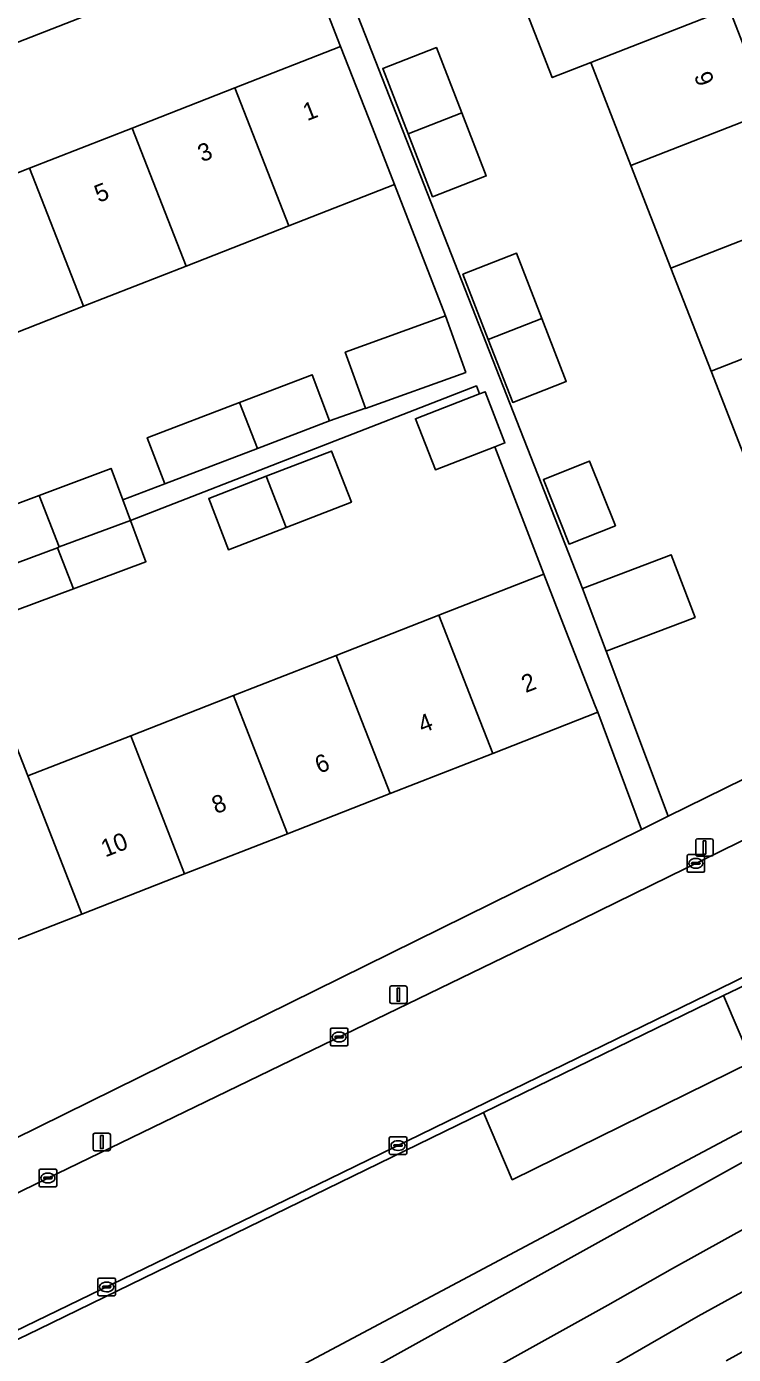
# Model space of a CAD drawing. Extents: x 159680 to 160786, y 387323 to 388340.
# Drawn here: x 160243.7 to 160284, y 387463 to 387538.8 of the extents above; entities that cross this region are included whole.
import ezdxf

# ---------------------------------------------------------------- set-up
doc = ezdxf.new("R2010")
doc.units = 0
for name, color, linetype in [('IMGEO_Erf', 7, 'Continuous'), ('IMGEO_Fietspad_open', 7, 'Continuous'), ('IMGEO_Groenvoorziening', 7, 'Continuous'), ('IMGEO_Kolk', 7, 'Continuous'), ('IMGEO_Lichtmast', 7, 'Continuous'), ('IMGEO_Pand', 7, 'Continuous'), ('IMGEO_Pand_nummerreeks', 7, 'Continuous'), ('IMGEO_Rijbaan_lokaal_open', 7, 'Continuous'), ('IMGEO_Voetpad_open', 7, 'Continuous')]:
    doc.layers.add(name, color=color, linetype=linetype)

msp = doc.modelspace()

# ---------------------------------------------------------------- linework, layer by layer
at = {"layer": 'IMGEO_Erf'}
for points in [[(160275.893, 387536.722), (160273.69, 387535.863), (160271.402, 387541.734), (160273.605, 387542.592), (160271.263, 387548.602), (160279.163, 387551.682), (160281.506, 387545.671), (160283.794, 387539.801), (160286.081, 387533.932), (160288.369, 387528.062), (160290.657, 387522.192), (160292.945, 387516.322), (160295.286, 387510.315), (160287.386, 387507.236), (160285.045, 387513.243), (160282.757, 387519.113), (160280.469, 387524.983), (160278.181, 387530.853)], [(160243.826, 387530.687), (160249.693, 387532.984), (160255.559, 387535.28), (160261.594, 387537.642), (160259.073, 387544.104), (160205.916, 387523.37), (160208.461, 387516.845), (160214.493, 387519.206), (160220.36, 387521.502), (160226.226, 387523.799), (160232.093, 387526.095), (160237.96, 387528.391)], [(160269.916, 387530.256), (160266.852, 387529.064), (160265.456, 387532.655), (160264.006, 387536.382), (160267.07, 387537.573), (160268.518, 387533.848)], [(160273.094, 387522.108), (160274.491, 387518.517), (160271.427, 387517.325), (160270.031, 387520.915), (160268.581, 387524.643), (160271.645, 387525.834)], [(160254.062, 387511.834), (160257.35, 387513.104), (160261.076, 387514.543), (160262.215, 387511.629), (160258.488, 387510.191), (160255.189, 387508.916)], [(160275.822, 387513.975), (160277.292, 387510.285), (160274.648, 387509.232), (160273.178, 387512.922)], [(160278.786, 387492.941), (160276.288, 387499.632), (160270.292, 387497.289), (160264.424, 387494.996), (160258.556, 387492.703), (160252.688, 387490.41), (160246.82, 387488.116), (160240.952, 387485.823), (160235.084, 387483.53), (160229.216, 387481.237), (160223.218, 387478.893), (160227.723, 387467.872), (160241.485, 387474.571)]]:
    msp.add_lwpolyline(points, close=True, dxfattribs=at)
for points in [[(160260.298, 387545.217), (160260.495, 387544.659), (160260.565, 387544.686), (160260.501, 387544.952), (160260.459, 387545.227), (160260.442, 387545.504), (160260.45, 387545.782), (160260.482, 387546.058), (160260.538, 387546.33), (160260.618, 387546.596), (160260.721, 387546.854), (160260.846, 387547.102), (160263.113, 387548.017), (160263.29, 387545.707), (160263.076, 387545.631), (160264.519, 387541.798), (160262.008, 387540.853), (160275.412, 387506.704), (160280.486, 387508.629), (160281.844, 387505.049), (160276.77, 387503.124), (160280.318, 387493.696), (160290.044, 387498.486)], [(160238.972, 387509.987), (160244.379, 387512.012), (160248.487, 387513.55), (160249.155, 387511.767), (160251.558, 387512.667), (160250.552, 387515.301), (160255.824, 387517.316), (160259.965, 387518.897), (160260.971, 387516.264), (160263.015, 387517.003), (160261.863, 387520.187), (160267.583, 387522.257), (160264.677, 387529.767), (160258.641, 387527.405), (160252.775, 387525.108), (160246.908, 387522.812), (160241.042, 387520.516)], [(160242.477, 387499.229), (160243.739, 387496), (160249.608, 387498.294), (160253.974, 387500), (160255.476, 387500.587), (160261.344, 387502.88), (160267.211, 387505.173), (160273.207, 387507.516), (160270.399, 387514.789), (160267.01, 387513.481), (160265.872, 387516.394), (160269.53, 387517.807), (160269.353, 387518.266), (160249.598, 387510.584), (160250.479, 387508.231), (160246.335, 387506.679), (160243.13, 387505.479)]]:
    msp.add_lwpolyline(points, dxfattribs=at)
at = {"layer": 'IMGEO_Fietspad_open'}
msp.add_lwpolyline([(160283.621, 387462.603), (160296.695, 387469.852), (160300.001, 387472.11), (160301.207, 387473.161), (160302.845, 387474.524), (160305.717, 387478.074), (160304.637, 387480.044), (160301.617, 387477.461), (160298.558, 387474.843), (160297.951, 387474.363), (160295.506, 387472.609), (160294.842, 387472.203), (160282.017, 387465.159), (160277.159, 387462.365)], dxfattribs=at)
at = {"layer": 'IMGEO_Groenvoorziening'}
for points in [[(160304.976, 387485.635), (160305.378, 387490.681), (160303.29, 387492.695), (160299.837, 387491.263), (160294.558, 387488.872), (160284.429, 387483.931), (160284.303, 387483.869), (160283.478, 387483.467), (160285.084, 387479.686), (160271.406, 387472.947), (160269.768, 387476.788), (160244.367, 387464.412), (160217.091, 387451.27)], [(160262.249, 387457.676), (160276.867, 387465.794), (160280.554, 387467.888), (160297.076, 387477.04)]]:
    msp.add_lwpolyline(points, dxfattribs=at)
for points in [[(160283.478, 387483.467), (160270.499, 387477.144), (160269.768, 387476.788), (160271.406, 387472.947), (160285.084, 387479.686)], [(160286.787, 387476.926), (160287.418, 387475.529), (160246.566, 387452.847), (160245.582, 387455.016)], [(160287.418, 387475.529), (160286.787, 387476.926), (160245.582, 387455.016), (160246.566, 387452.847)]]:
    msp.add_lwpolyline(points, close=True, dxfattribs=at)
at = {"layer": 'IMGEO_Kolk'}
for p, q in [((160281.463, 387491.509), (160282.315, 387491.509)), ((160281.388, 387490.583), (160281.388, 387491.435)), ((160281.647, 387491.003), (160281.647, 387491.015)), ((160282.085, 387490.966), (160281.687, 387490.966)), ((160281.69, 387491.052), (160282.088, 387491.052)), ((160281.899, 387490.729), (160281.874, 387490.729)), ((160281.876, 387491.289), (160281.901, 387491.289)), ((160282.131, 387491.015), (160282.131, 387491.003)), ((160282.389, 387491.435), (160282.389, 387490.583)), ((160282.315, 387490.509), (160281.463, 387490.509)), ((160261.091, 387481.597), (160261.943, 387481.597)), ((160261.016, 387480.671), (160261.016, 387481.523)), ((160261.275, 387481.091), (160261.275, 387481.103)), ((160261.713, 387481.054), (160261.315, 387481.054)), ((160261.318, 387481.14), (160261.716, 387481.14)), ((160261.504, 387481.377), (160261.529, 387481.377)), ((160261.759, 387481.103), (160261.759, 387481.091)), ((160262.017, 387481.523), (160262.017, 387480.671)), ((160261.943, 387480.597), (160261.091, 387480.597)), ((160261.527, 387480.817), (160261.502, 387480.817)), ((160264.38, 387474.474), (160264.38, 387475.326)), ((160264.455, 387475.4), (160265.307, 387475.4)), ((160264.639, 387474.894), (160264.639, 387474.906)), ((160265.077, 387474.857), (160264.679, 387474.857)), ((160264.682, 387474.943), (160265.08, 387474.943)), ((160264.868, 387475.18), (160264.893, 387475.18)), ((160265.123, 387474.906), (160265.123, 387474.894)), ((160265.381, 387475.326), (160265.381, 387474.474)), ((160265.307, 387474.4), (160264.455, 387474.4)), ((160264.891, 387474.62), (160264.866, 387474.62)), ((160244.378, 387472.622), (160244.378, 387473.474)), ((160244.453, 387473.548), (160245.305, 387473.548)), ((160244.866, 387473.328), (160244.891, 387473.328)), ((160245.379, 387473.474), (160245.379, 387472.622)), ((160245.305, 387472.548), (160244.453, 387472.548)), ((160244.637, 387473.042), (160244.637, 387473.054)), ((160245.075, 387473.005), (160244.677, 387473.005)), ((160244.68, 387473.091), (160245.078, 387473.091)), ((160244.889, 387472.768), (160244.864, 387472.768)), ((160245.121, 387473.054), (160245.121, 387473.042)), ((160247.733, 387466.405), (160247.733, 387467.257)), ((160247.808, 387467.331), (160248.66, 387467.331)), ((160248.734, 387467.257), (160248.734, 387466.405)), ((160247.992, 387466.825), (160247.992, 387466.837)), ((160248.43, 387466.788), (160248.032, 387466.788)), ((160248.035, 387466.874), (160248.433, 387466.874)), ((160248.244, 387466.551), (160248.219, 387466.551)), ((160248.221, 387467.111), (160248.246, 387467.111)), ((160248.476, 387466.837), (160248.476, 387466.825)), ((160248.66, 387466.331), (160247.808, 387466.331))]:
    msp.add_line(p, q, dxfattribs=at)
for points in [[(160281.463, 387491.509), (160282.315, 387491.509)], [(160281.388, 387490.583), (160281.388, 387491.435)], [(160282.389, 387491.435), (160282.389, 387490.583)], [(160282.315, 387490.509), (160281.463, 387490.509)], [(160261.091, 387481.597), (160261.943, 387481.597)], [(160261.016, 387480.671), (160261.016, 387481.523)], [(160262.017, 387481.523), (160262.017, 387480.671)], [(160261.943, 387480.597), (160261.091, 387480.597)], [(160264.38, 387474.474), (160264.38, 387475.326)], [(160264.455, 387475.4), (160265.307, 387475.4)], [(160265.381, 387475.326), (160265.381, 387474.474)], [(160265.307, 387474.4), (160264.455, 387474.4)], [(160244.378, 387472.622), (160244.378, 387473.474)], [(160244.453, 387473.548), (160245.305, 387473.548)], [(160245.379, 387473.474), (160245.379, 387472.622)], [(160245.305, 387472.548), (160244.453, 387472.548)], [(160247.733, 387466.405), (160247.733, 387467.257)], [(160247.808, 387467.331), (160248.66, 387467.331)], [(160248.734, 387467.257), (160248.734, 387466.405)], [(160248.66, 387466.331), (160247.808, 387466.331)]]:
    msp.add_lwpolyline(points, dxfattribs=at)
for centre, radius, start, end in [((160281.465, 387491.433), 0.0765, 91.55205, 178.44795), ((160281.465, 387491.433), 0.0765, 91.55205, 178.44795), ((160282.313, 387491.433), 0.0765, 1.55205, 88.44795), ((160282.313, 387491.433), 0.0765, 1.55205, 88.44795), ((160281.687, 387491.012), 0.0403, 85.87752, 175.75265), ((160281.684, 387491.002), 0.0366, 178.93798, 274.71019), ((160282.088, 387491.009), 0.043, 264.86636, 352.45326), ((160282.092, 387491.014), 0.0386, 1.73085, 96.63898), ((160281.465, 387490.585), 0.0765, 181.55205, 268.44795), ((160281.465, 387490.585), 0.0765, 181.55205, 268.44795), ((160282.313, 387490.585), 0.0765, 271.55205, 358.44795), ((160282.313, 387490.585), 0.0765, 271.55205, 358.44795), ((160261.093, 387481.521), 0.0765, 91.55205, 178.44795), ((160261.093, 387481.521), 0.0765, 91.55205, 178.44795), ((160261.941, 387481.521), 0.0765, 1.55205, 88.44795), ((160261.941, 387481.521), 0.0765, 1.55205, 88.44795), ((160261.315, 387481.1), 0.0403, 85.87752, 175.75265), ((160261.312, 387481.09), 0.0366, 178.93798, 274.71019), ((160261.716, 387481.097), 0.043, 264.86636, 352.45326), ((160261.72, 387481.102), 0.0386, 1.73085, 96.63898), ((160261.093, 387480.673), 0.0765, 181.55205, 268.44795), ((160261.093, 387480.673), 0.0765, 181.55205, 268.44795), ((160261.941, 387480.673), 0.0765, 271.55205, 358.44795), ((160261.941, 387480.673), 0.0765, 271.55205, 358.44795), ((160264.457, 387475.324), 0.0765, 91.55205, 178.44795), ((160264.457, 387475.324), 0.0765, 91.55205, 178.44795), ((160264.679, 387474.903), 0.0403, 85.87752, 175.75265), ((160264.676, 387474.893), 0.0366, 178.93798, 274.71019), ((160265.08, 387474.9), 0.043, 264.86636, 352.45326), ((160265.084, 387474.905), 0.0386, 1.73085, 96.63898), ((160265.305, 387475.324), 0.0765, 1.55205, 88.44795), ((160265.305, 387475.324), 0.0765, 1.55205, 88.44795), ((160264.457, 387474.476), 0.0765, 181.55205, 268.44795), ((160264.457, 387474.476), 0.0765, 181.55205, 268.44795), ((160265.305, 387474.476), 0.0765, 271.55205, 358.44795), ((160265.305, 387474.476), 0.0765, 271.55205, 358.44795), ((160244.455, 387473.472), 0.0765, 91.55205, 178.44795), ((160244.455, 387473.472), 0.0765, 91.55205, 178.44795), ((160245.303, 387473.472), 0.0765, 1.55205, 88.44795), ((160245.303, 387473.472), 0.0765, 1.55205, 88.44795), ((160244.455, 387472.624), 0.0765, 181.55205, 268.44795), ((160244.455, 387472.624), 0.0765, 181.55205, 268.44795), ((160244.677, 387473.051), 0.0403, 85.87752, 175.75265), ((160244.674, 387473.041), 0.0366, 178.93798, 274.71019), ((160245.078, 387473.048), 0.043, 264.86636, 352.45326), ((160245.082, 387473.053), 0.0386, 1.73085, 96.63898), ((160245.303, 387472.624), 0.0765, 271.55205, 358.44795), ((160245.303, 387472.624), 0.0765, 271.55205, 358.44795), ((160247.81, 387467.255), 0.0765, 91.55205, 178.44795), ((160247.81, 387467.255), 0.0765, 91.55205, 178.44795), ((160248.658, 387467.255), 0.0765, 1.55205, 88.44795), ((160248.658, 387467.255), 0.0765, 1.55205, 88.44795), ((160248.032, 387466.834), 0.0403, 85.87752, 175.75265), ((160248.029, 387466.824), 0.0366, 178.93798, 274.71019), ((160248.433, 387466.831), 0.043, 264.86636, 352.45326), ((160248.437, 387466.836), 0.0386, 1.73085, 96.63898), ((160247.81, 387466.407), 0.0765, 181.55205, 268.44795), ((160247.81, 387466.407), 0.0765, 181.55205, 268.44795), ((160248.658, 387466.407), 0.0765, 271.55205, 358.44795), ((160248.658, 387466.407), 0.0765, 271.55205, 358.44795)]:
    msp.add_arc(centre, radius, start, end, dxfattribs=at)
for centre, major_axis, ratio, start_param, end_param in [((160281.875, 387491.009), (-0.387, 0.002), 0.722429, 4.712389, 7.853982), ((160281.9, 387491.009), (-0.39, 0.002), 0.717154, 1.570796, 4.712389), ((160261.503, 387481.097), (-0.387, 0.002), 0.722429, 4.712389, 7.853982), ((160261.528, 387481.097), (-0.39, 0.002), 0.717154, 1.570796, 4.712389), ((160264.867, 387474.9), (-0.387, 0.002), 0.722429, 4.712389, 7.853982), ((160264.892, 387474.9), (-0.39, 0.002), 0.717154, 1.570796, 4.712389), ((160244.865, 387473.048), (-0.387, 0.002), 0.722429, 4.712389, 7.853982), ((160244.89, 387473.048), (-0.39, 0.002), 0.717154, 1.570796, 4.712389), ((160248.22, 387466.831), (-0.387, 0.002), 0.722429, 4.712389, 7.853982), ((160248.245, 387466.831), (-0.39, 0.002), 0.717154, 1.570796, 4.712389)]:
    msp.add_ellipse(centre, major_axis=major_axis, ratio=ratio, start_param=start_param, end_param=end_param, dxfattribs=at)
at = {"layer": 'IMGEO_Lichtmast'}
for p, q in [((160281.881, 387491.519), (160281.881, 387492.319)), ((160281.881, 387492.319), (160281.881, 387491.519)), ((160281.981, 387492.419), (160282.771, 387492.419)), ((160282.771, 387492.419), (160281.981, 387492.419)), ((160282.871, 387492.319), (160282.871, 387491.519)), ((160282.871, 387491.519), (160282.871, 387492.319)), ((160282.771, 387491.419), (160281.981, 387491.419)), ((160281.981, 387491.419), (160282.771, 387491.419)), ((160264.401, 387483.114), (160264.401, 387483.914)), ((160264.401, 387483.914), (160264.401, 387483.114)), ((160264.501, 387484.014), (160265.291, 387484.014)), ((160265.291, 387484.014), (160264.501, 387484.014)), ((160265.391, 387483.914), (160265.391, 387483.114)), ((160265.391, 387483.114), (160265.391, 387483.914)), ((160265.291, 387483.014), (160264.501, 387483.014)), ((160264.501, 387483.014), (160265.291, 387483.014)), ((160247.555, 387475.605), (160248.345, 387475.605)), ((160248.345, 387475.605), (160247.555, 387475.605)), ((160247.455, 387474.705), (160247.455, 387475.505)), ((160247.455, 387475.505), (160247.455, 387474.705)), ((160248.445, 387475.505), (160248.445, 387474.705)), ((160248.445, 387474.705), (160248.445, 387475.505)), ((160248.345, 387474.605), (160247.555, 387474.605)), ((160247.555, 387474.605), (160248.345, 387474.605))]:
    msp.add_line(p, q, dxfattribs=at)
for points in [[(160282.301, 387492.294), (160282.451, 387492.294), (160282.451, 387491.544), (160282.301, 387491.544), (160282.301, 387492.294)], [(160264.821, 387483.889), (160264.971, 387483.889), (160264.971, 387483.139), (160264.821, 387483.139), (160264.821, 387483.889)], [(160247.875, 387475.48), (160248.025, 387475.48), (160248.025, 387474.73), (160247.875, 387474.73), (160247.875, 387475.48)]]:
    msp.add_lwpolyline(points, dxfattribs=at)
for centre, start, end in [((160281.981, 387492.319), 90, 180), ((160281.981, 387492.319), 90, 180), ((160282.771, 387492.319), 0, 90), ((160282.771, 387492.319), 360, 90), ((160281.981, 387491.519), 180, 270), ((160281.981, 387491.519), 180, 270), ((160282.771, 387491.519), 270, 0), ((160282.771, 387491.519), 270, 0), ((160264.501, 387483.914), 90, 180), ((160264.501, 387483.914), 90, 180), ((160265.291, 387483.914), 0, 90), ((160265.291, 387483.914), 360, 90), ((160264.501, 387483.114), 180, 270), ((160264.501, 387483.114), 180, 270), ((160265.291, 387483.114), 270, 0), ((160265.291, 387483.114), 270, 0), ((160247.555, 387475.505), 90, 180), ((160247.555, 387475.505), 90, 180), ((160248.345, 387475.505), 0, 90), ((160248.345, 387475.505), 360, 90), ((160247.555, 387474.705), 180, 270), ((160247.555, 387474.705), 180, 270), ((160248.345, 387474.705), 270, 0), ((160248.345, 387474.705), 270, 0)]:
    msp.add_arc(centre, 0.1, start, end, dxfattribs=at)
at = {"layer": 'IMGEO_Pand'}
for points in [[(160281.506, 387545.671), (160273.605, 387542.592), (160271.402, 387541.734), (160273.69, 387535.863), (160275.893, 387536.722), (160283.794, 387539.801)], [(160275.893, 387536.722), (160278.181, 387530.853), (160286.081, 387533.932), (160283.794, 387539.801)], [(160258.641, 387527.405), (160264.677, 387529.767), (160263.416, 387532.987), (160261.594, 387537.642), (160255.559, 387535.28)], [(160267.07, 387537.573), (160264.006, 387536.382), (160265.456, 387532.655), (160268.518, 387533.848)], [(160252.775, 387525.108), (160258.641, 387527.405), (160255.559, 387535.28), (160249.693, 387532.984)], [(160288.369, 387528.062), (160286.081, 387533.932), (160278.181, 387530.853), (160280.469, 387524.983)], [(160266.852, 387529.064), (160269.916, 387530.256), (160268.518, 387533.848), (160265.456, 387532.655)], [(160249.693, 387532.984), (160243.826, 387530.687), (160246.908, 387522.812), (160252.775, 387525.108)], [(160241.042, 387520.516), (160246.908, 387522.812), (160243.826, 387530.687), (160237.96, 387528.391)], [(160280.469, 387524.983), (160282.757, 387519.113), (160290.657, 387522.192), (160288.369, 387528.062)], [(160270.031, 387520.915), (160273.094, 387522.108), (160271.645, 387525.834), (160268.581, 387524.643)], [(160267.583, 387522.257), (160261.863, 387520.187), (160263.015, 387517.003), (160263.027, 387516.969), (160268.748, 387519.039)], [(160273.094, 387522.108), (160270.031, 387520.915), (160271.427, 387517.325), (160274.491, 387518.517)], [(160282.757, 387519.113), (160285.045, 387513.243), (160292.945, 387516.322), (160290.657, 387522.192)], [(160255.824, 387517.316), (160256.852, 387514.69), (160260.971, 387516.264), (160259.965, 387518.897)], [(160256.852, 387514.69), (160255.824, 387517.316), (160250.552, 387515.301), (160251.558, 387512.667)], [(160269.854, 387517.932), (160269.53, 387517.807), (160265.872, 387516.394), (160267.01, 387513.481), (160270.399, 387514.789), (160270.981, 387515.014)], [(160257.35, 387513.104), (160258.488, 387510.191), (160262.215, 387511.629), (160261.076, 387514.543)], [(160249.155, 387511.767), (160248.487, 387513.55), (160244.379, 387512.012), (160245.53, 387509.07), (160249.598, 387510.584)], [(160273.178, 387512.922), (160274.648, 387509.232), (160277.292, 387510.285), (160275.822, 387513.975)], [(160258.488, 387510.191), (160257.35, 387513.104), (160254.062, 387511.834), (160255.189, 387508.916)], [(160244.379, 387512.012), (160238.972, 387509.987), (160239.697, 387508.041), (160239.841, 387507.656), (160242.08, 387508.538), (160242.309, 387507.87), (160245.417, 387509.027), (160245.53, 387509.07)], [(160246.335, 387506.679), (160250.479, 387508.231), (160249.598, 387510.584), (160245.53, 387509.07), (160245.417, 387509.027)], [(160245.417, 387509.027), (160242.309, 387507.87), (160242.396, 387507.617), (160243.13, 387505.479), (160246.335, 387506.679)], [(160275.412, 387506.704), (160276.77, 387503.124), (160281.844, 387505.049), (160280.486, 387508.629)], [(160269.232, 387500), (160270.292, 387497.289), (160276.288, 387499.632), (160276.144, 387500), (160274.468, 387504.29), (160273.207, 387507.516), (160267.211, 387505.173)], [(160267.211, 387505.173), (160261.344, 387502.88), (160262.469, 387500), (160264.424, 387494.996), (160270.292, 387497.289), (160269.232, 387500)], [(160255.705, 387500), (160258.556, 387492.703), (160264.424, 387494.996), (160262.469, 387500), (160261.344, 387502.88), (160255.476, 387500.587)], [(160255.476, 387500.587), (160253.974, 387500), (160249.608, 387498.294), (160252.688, 387490.41), (160258.556, 387492.703), (160255.705, 387500)], [(160243.739, 387496), (160242.477, 387499.229), (160236.609, 387496.937), (160237.871, 387493.707), (160240.952, 387485.823), (160246.82, 387488.116)], [(160249.608, 387498.294), (160243.739, 387496), (160246.82, 387488.116), (160252.688, 387490.41)]]:
    msp.add_lwpolyline(points, close=True, dxfattribs=at)
at = {"layer": 'IMGEO_Rijbaan_lokaal_open'}
msp.add_lwpolyline([(160238.595, 387462.168), (160260.972, 387472.997), (160284.062, 387484.245), (160294.302, 387489.299), (160298.001, 387490.97), (160302.229, 387492.724), (160299.617, 387498.991), (160291.32, 387495.632), (160273.34, 387486.815), (160244.805, 387473.011), (160212.305, 387457.22)], dxfattribs=at)
at = {"layer": 'IMGEO_Voetpad_open'}
for points in [[(160144.614, 387503.473), (160142.628, 387504.592), (160131.07, 387500), (160118.877, 387495.156), (160118.682, 387495.073), (160118.883, 387494.62), (160119.137, 387494.046), (160120.792, 387492.803), (160139.164, 387500), (160141.985, 387501.105), (160145.626, 387499.854), (160204.532, 387522.83), (160205.916, 387523.37), (160259.073, 387544.104), (160260.495, 387544.659)], [(160259.073, 387544.104), (160261.594, 387537.642), (160263.416, 387532.987), (160264.677, 387529.767), (160267.583, 387522.257), (160268.748, 387519.039), (160263.027, 387516.969), (160263.015, 387517.003), (160260.971, 387516.264), (160256.852, 387514.69), (160251.558, 387512.667), (160249.155, 387511.767), (160249.598, 387510.584), (160269.353, 387518.266), (160269.53, 387517.807), (160269.854, 387517.932), (160270.981, 387515.014), (160270.399, 387514.789), (160273.207, 387507.516), (160274.468, 387504.29), (160276.144, 387500), (160276.288, 387499.632), (160278.786, 387492.941), (160280.318, 387493.696), (160276.77, 387503.124), (160275.412, 387506.704), (160262.008, 387540.853)], [(160304.769, 387501.287), (160302.86, 387504.739), (160290.044, 387498.486), (160280.318, 387493.696), (160278.786, 387492.941), (160241.485, 387474.571), (160227.723, 387467.872), (160226.209, 387467.135), (160169.278, 387439.422), (160167.907, 387438.735), (160164.291, 387436.979), (160158.178, 387434.182), (160152.225, 387431.238), (160146.292, 387428.305), (160142.001, 387426.255), (160138.326, 387424.631)], [(160244.805, 387473.011), (160273.34, 387486.815), (160291.32, 387495.632), (160299.617, 387498.991), (160299.685, 387499.019), (160300.244, 387499.245), (160302.509, 387500.144)], [(160217.091, 387451.27), (160244.367, 387464.412), (160269.768, 387476.788), (160270.499, 387477.144), (160283.478, 387483.467), (160284.303, 387483.869), (160284.429, 387483.931), (160294.558, 387488.872), (160299.837, 387491.263), (160303.29, 387492.695), (160303.151, 387493.105), (160303.137, 387493.1), (160302.229, 387492.724), (160298.001, 387490.97), (160294.302, 387489.299), (160284.062, 387484.245), (160260.972, 387472.997), (160238.595, 387462.168)], [(160304.148, 387483.443), (160303.552, 387482.65), (160303.035, 387482.048), (160297.748, 387477.449), (160297.076, 387477.04), (160280.554, 387467.888), (160276.867, 387465.794), (160262.249, 387457.676), (160258.008, 387455.524), (160243.399, 387446.858), (160208.101, 387424.823), (160160.574, 387395.054), (160155.098, 387391.826)], [(160159.013, 387390.625), (160161.282, 387391.902), (160161.569, 387392.079), (160172.972, 387399.218), (160174.71, 387400.186), (160188.751, 387409.025), (160201.505, 387416.998), (160218.594, 387427.633), (160232.498, 387436.379), (160245.641, 387444.527), (160257.213, 387451.206), (160264.291, 387455.191), (160271.867, 387459.381), (160277.159, 387462.365), (160282.017, 387465.159), (160294.842, 387472.203), (160295.506, 387472.609), (160297.951, 387474.363), (160298.558, 387474.843), (160301.617, 387477.461), (160304.637, 387480.044), (160305.174, 387480.615), (160305.812, 387481.41)], [(160212.305, 387457.22), (160244.805, 387473.011)]]:
    msp.add_lwpolyline(points, dxfattribs=at)

# ---------------------------------------------------------------- texts
at = {"layer": 'IMGEO_Pand_nummerreeks'}
for s, rotation, p in [('9', 291.2936, (160281.765, 387535.974)), ('1', 21.37607, (160259.687, 387533.373)), ('3', 21.37607, (160253.678, 387531.021)), ('5', 21.37607, (160247.774, 387528.711)), ('2', 21.34569, (160272.166, 387500.727)), ('4', 21.34485, (160266.268, 387498.423)), ('6', 21.34485, (160260.372, 387496.118)), ('8', 21.34485, (160254.479, 387493.815)), ('10', 21.34485, (160248.153, 387491.344))]:
    msp.add_text(s, height=1, rotation=rotation, dxfattribs=at).set_placement(p)

doc.saveas('drawing.dxf')
